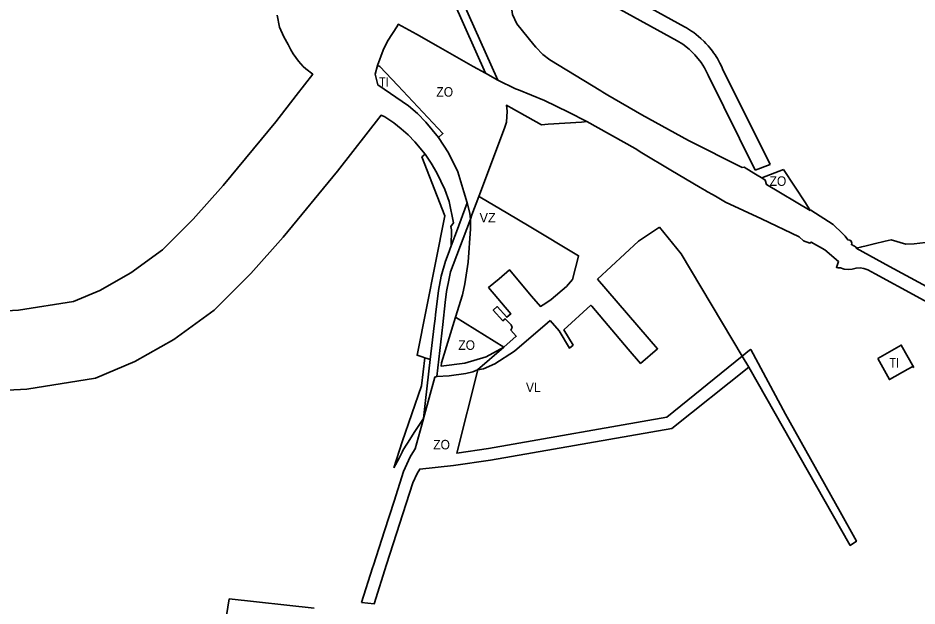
# Model space of a CAD drawing. Extents: x -650971 to -642489, y -1074311 to -1062745.
# Drawn here: x -647077 to -645941, y -1069362 to -1068619 of the extents above; entities that cross this region are included whole.
import ezdxf

# ---------------------------------------------------------------- set-up
doc = ezdxf.new("R2010")
doc.units = 0
doc.header["$LTSCALE"] = 4.8
for name, color, linetype, lineweight in [('13', 7, 'Continuous', 35), ('15', 7, 'Continuous', 35), ('24', 7, 'Continuous', 35), ('30', 7, 'Continuous', 35), ('34', 7, 'Continuous', 35), ('36', 7, 'Continuous', 35), ('42', 7, 'Continuous', 35), ('62', 7, 'Continuous', 35)]:
    doc.layers.add(name, color=color, linetype=linetype, lineweight=lineweight)

msp = doc.modelspace()

# ---------------------------------------------------------------- linework, layer by layer
at = {"layer": '13'}
msp.add_lwpolyline([(-646842.441, -1069555.283), (-646809.879, -1069353.002), (-646702.425, -1069364.771)], dxfattribs=at)
at = {"layer": '15'}
msp.add_lwpolyline([(-646161.484, -1069046.228), (-646152.26, -1069038.76), (-646150.87, -1069037.64), (-646107, -1069119.41), (-646037.99, -1069242.88), (-646017.15, -1069280.19), (-646025.14, -1069285.394), (-646153.307, -1069059.947)], close=True, dxfattribs=at)
at = {"layer": '24'}
msp.add_line((-646126.317, -1068803.654), (-646145.083, -1068810.83), dxfattribs=at)
for points in [[(-646513.45, -1068476.025), (-646234.342, -1068629.892), (-646232.141, -1068631.139), (-646229.573, -1068632.68), (-646225.838, -1068635.097), (-646222.933, -1068637.129), (-646219.751, -1068639.522), (-646216.809, -1068641.902), (-646213.784, -1068644.532), (-646209.607, -1068648.501), (-646207.455, -1068650.718), (-646204.769, -1068653.669), (-646202.389, -1068656.475), (-646200.727, -1068658.552), (-646199.218, -1068660.531), (-646197.683, -1068662.645), (-646195.834, -1068665.339), (-646194.492, -1068667.409), (-646192.895, -1068670.012), (-646191.425, -1068672.562), (-646189.676, -1068675.819), (-646187.091, -1068681.19), (-646186.901, -1068681.614), (-646186.371, -1068682.825), (-646126.317, -1068803.654)], [(-646556.22, -1068515.84), (-646555, -1068519.38), (-646526.1, -1068598.55), (-646486.23, -1068688.54)], [(-646470.65, -1068697.38), (-646515.09, -1068597.29), (-646516.07, -1068595.08), (-646519.14, -1068587.06), (-646521.81, -1068580.69), (-646535.84, -1068539.8), (-646541.06, -1068524.58), (-646545.57, -1068511.42)], [(-646495.416, -1068512.888), (-646487.92, -1068516.87), (-646477.41, -1068526.45), (-646469.51, -1068538.15), (-646461.14, -1068556.34), (-646458.03, -1068569.26), (-646451.82, -1068614.31), (-646446.54, -1068626.14), (-646425.11, -1068652.37), (-646422.32, -1068655.58), (-646413.45, -1068664.71), (-646404.83, -1068671.52), (-646340.36, -1068710.915), (-646337.93, -1068712.4), (-646331.26, -1068716.25), (-646288.59, -1068740.88), (-646229.44, -1068773.53), (-646161.45, -1068807.54), (-646159.1, -1068807.43), (-646150.26, -1068812.81)], [(-646145.083, -1068810.83), (-646204.654, -1068690.937), (-646209.179, -1068681.795), (-646213.659, -1068674.696), (-646221.348, -1068665.144), (-646228.691, -1068658.051), (-646236.707, -1068651.891), (-646243.997, -1068647.407), (-646493.511, -1068509.855)], [(-647128.674, -1068991.167), (-647076.422, -1068988.18), (-647006.63, -1068977.08), (-646973.61, -1068963.135), (-646934.465, -1068940.759), (-646894.206, -1068911.595), (-646855.506, -1068872.883), (-646817.718, -1068830.545), (-646751.116, -1068749.975), (-646725.374, -1068716.786), (-646704.316, -1068689.698), (-646712.93, -1068683), (-646716.39, -1068679.8), (-646722.6, -1068673.11), (-646729.34, -1068663.94), (-646732.25, -1068659.06), (-646735.62, -1068652.21), (-646740.91, -1068642.34), (-646746.32, -1068630.23), (-646749.35, -1068615.18)], [(-646486.23, -1068688.54), (-646501.64, -1068679.81), (-646545.73, -1068654.81), (-646573.14, -1068638.98), (-646596.28, -1068626.52), (-646597.4, -1068628.74), (-646609.7, -1068647.84), (-646615.19, -1068659.11), (-646622.68, -1068678.75)], [(-646622.68, -1068678.75), (-646625.35, -1068689.7), (-646622.01, -1068703.3), (-646583.49, -1068729.76), (-646571.91, -1068739.54), (-646561.5, -1068750.22), (-646545.32, -1068769.89)], [(-646357.87, -1068749.64), (-646380.94, -1068737.81), (-646411.3, -1068723.11), (-646444.51, -1068709.64), (-646448.02, -1068707.99), (-646470.65, -1068697.38)], [(-646562.49, -1068790.69), (-646575.28, -1068775.04), (-646583.98, -1068766.42), (-646592.53, -1068758.66), (-646601.86, -1068751.01), (-646613.44, -1068743.65), (-646617.991, -1068741.503), (-646673.05, -1068812.491), (-646741.85, -1068895.719), (-646782.784, -1068941.581), (-646829.104, -1068987.917), (-646880.163, -1069024.903), (-646929.186, -1069052.925), (-646978.92, -1069073.93), (-647065.688, -1069087.73), (-647123.648, -1069091.043), (-647197.498, -1069094.255), (-647270.522, -1069094.255), (-647344.902, -1069091.02), (-647426.417, -1069084.624), (-647511.94, -1069076.703), (-647708.401, -1069056.275), (-647756.441, -1069053.207), (-647798.631, -1069052.508)], [(-646208.7, -1068836.39), (-646214.92, -1068832.85), (-646251.73, -1068811.04), (-646288.37, -1068789.04), (-646297.08, -1068783.8), (-646357.87, -1068749.64)], [(-646545.32, -1068769.89), (-646532.92, -1068788.95), (-646521.18, -1068812.95), (-646513.27, -1068838.37), (-646509.323, -1068852.529)], [(-646529.44, -1068906.81), (-646528.92, -1068886.55), (-646530.06, -1068882.16), (-646526.64, -1068877.47), (-646532.16, -1068850.47), (-646537.35, -1068835.56), (-646547.68, -1068814.22), (-646554.8, -1068801.98), (-646562.49, -1068790.69)], [(-646150.26, -1068812.81), (-646146.85, -1068814.88), (-646140.73, -1068818.61), (-646136.99, -1068820.88)], [(-646136.99, -1068820.88), (-646132.62, -1068823.54), (-646130.68, -1068829.21), (-646075.56, -1068861.95)], [(-646195.52, -1068843.92), (-646199.24, -1068841.79), (-646205.48, -1068838.23), (-646208.7, -1068836.39)], [(-645896.91, -1068994.75), (-645940.77, -1068970.74), (-645993.5, -1068942.1), (-646002.95, -1068936.95), (-646007.7, -1068935.18), (-646012.64, -1068934.34), (-646017.6, -1068934.89), (-646022.77, -1068936.12), (-646027.69, -1068936.6), (-646032.61, -1068936.1), (-646037.5, -1068934.7), (-646040.65, -1068934.59), (-646042.5, -1068933.91), (-646039.84, -1068926.67), (-646057.13, -1068911.62), (-646074.51, -1068901.9), (-646076.09, -1068903.48), (-646084.1, -1068900.51), (-646089.63, -1068895.5), (-646137.23, -1068872.6), (-646182.57, -1068851.3), (-646195.52, -1068843.92)], [(-646509.323, -1068852.529), (-646510.56, -1068855.86), (-646521.63, -1068885.74), (-646529.44, -1068906.81)], [(-646075.56, -1068861.95), (-646074.78, -1068861.51), (-646046.48, -1068879.92), (-646034.65, -1068891.12), (-646031.31, -1068894.32), (-646028.18, -1068898.89), (-646025.57, -1068899.39), (-646023.92, -1068900.73), (-646023.13, -1068903.12), (-646023.56, -1068905.05), (-646017.39, -1068908.42), (-646017.55, -1068909.75)], [(-646547.413, -1069071.71), (-646539.77, -1069006.25), (-646537.02, -1068978.44), (-646535.13, -1068964.38), (-646532.13, -1068948), (-646530.08, -1068939.43), (-646526.81, -1068930.69), (-646505.17, -1068872.78)], [(-646505.17, -1068872.78), (-646505.12, -1068885.31), (-646507.91, -1068927.47), (-646512.07, -1068954.68), (-646514.91, -1068968.48), (-646524, -1068997)], [(-646017.55, -1068909.75), (-645975.31, -1068932.8), (-645933.28, -1068955.74), (-645892.77, -1068977.86), (-645856.26, -1068997.79)], [(-646524, -1068997), (-646541.71, -1069054.76), (-646542, -1069059), (-646512, -1069055), (-646485, -1069047), (-646462.98, -1069034.61), (-646496.317, -1069063.61)], [(-646601.82, -1069187.25), (-646591.26, -1069154.54), (-646566.82, -1069083.62), (-646562.61, -1069048.08)], [(-646555.84, -1069050.22), (-646561.88, -1069102.18), (-646562.35, -1069106.21), (-646564.54, -1069125.08)], [(-646562.61, -1069048.08), (-646559.8, -1069048.98), (-646555.84, -1069050.22)], [(-646496.317, -1069063.61), (-646502, -1069066), (-646511, -1069068), (-646532, -1069071), (-646547.413, -1069071.71)], [(-646564.54, -1069125.08), (-646575.4, -1069141.46), (-646582.46, -1069152.81), (-646583.89, -1069155.1), (-646585.42, -1069157.56), (-646586.97, -1069160.06), (-646590.38, -1069165.55), (-646591.4, -1069167.48), (-646595.32, -1069174.92), (-646601.82, -1069187.25)]]:
    msp.add_lwpolyline(points, dxfattribs=at)
at = {"layer": '30'}
for points in [[(-646545.32, -1068769.89), (-646561.5, -1068750.22), (-646571.91, -1068739.54), (-646583.49, -1068729.76), (-646622.01, -1068703.3), (-646625.35, -1068689.7), (-646622.68, -1068678.75)], [(-646622.68, -1068678.75), (-646619.74, -1068680.15), (-646596.93, -1068704.15), (-646539.78, -1068764.65), (-646545.32, -1068769.89)], [(-646562.61, -1069048.08), (-646566.25, -1069046.92), (-646572.42, -1069044.94), (-646537.3, -1068868.95), (-646566.34, -1068794.32), (-646562.49, -1068790.69)], [(-646562.49, -1068790.69), (-646554.8, -1068801.98), (-646547.68, -1068814.22), (-646537.35, -1068835.56), (-646532.16, -1068850.47), (-646526.64, -1068877.47), (-646530.06, -1068882.16), (-646528.92, -1068886.55), (-646529.44, -1068906.81)], [(-646529.44, -1068906.81), (-646533.28, -1068917.17), (-646536.54, -1068925.95), (-646542.16, -1068945.12), (-646545.42, -1068963.3), (-646549.17, -1068993.71), (-646549.81, -1068998.88), (-646550.89, -1069007.7), (-646555.84, -1069050.22)], [(-645990.13, -1069049.3), (-645960.67, -1069032.26), (-645944.69, -1069060.7)], [(-646555.84, -1069050.22), (-646559.8, -1069048.98), (-646562.61, -1069048.08)], [(-645944.69, -1069060.7), (-645946.84, -1069059.58), (-645952.21, -1069062.4), (-645975.48, -1069075.71), (-645990.13, -1069049.3)]]:
    msp.add_lwpolyline(points, dxfattribs=at)
at = {"layer": '34'}
for points in [[(-646344.49, -1068948.736), (-646292.75, -1068900.72), (-646266.118, -1068883.048)], [(-646266.118, -1068883.048), (-646238.632, -1068916.799), (-646161.484, -1069046.228)], [(-646404.269, -1069001.033), (-646393.09, -1069014.234), (-646379.973, -1069035.889), (-646375.346, -1069032.07), (-646386.936, -1069012.936), (-646352.71, -1068981.82), (-646351.638, -1068983.08), (-646351.641, -1068983.083), (-646305.65, -1069037.39), (-646290.099, -1069055.423), (-646268.528, -1069036.82), (-646344.49, -1068948.736)], [(-646495.89, -1069063.531), (-646488.537, -1069062.169), (-646474.13, -1069055.83), (-646449.419, -1069039.805), (-646425.52, -1069019.41), (-646410.96, -1069006.99), (-646404.269, -1069001.033)], [(-646161.484, -1069046.228), (-646256.824, -1069123.414), (-646482.211, -1069162.813), (-646522.35, -1069168.648), (-646495.89, -1069063.531)]]:
    msp.add_lwpolyline(points, dxfattribs=at)
at = {"layer": '36'}
for points in [[(-646494.52, -1068844.29), (-646492.73, -1068845.01), (-646457.86, -1068865.8), (-646430.86, -1068881.89), (-646368.3, -1068919.19), (-646368.42, -1068919.59), (-646376.02, -1068949.34), (-646383.86, -1068958.24), (-646403.13, -1068974.41), (-646409.67, -1068979.3), (-646416.71, -1068983.21), (-646427.77, -1068970.39), (-646455.78, -1068936.87), (-646468.83, -1068948.26), (-646482.2, -1068959.52), (-646454.21, -1068992.73), (-646459.25, -1068996.98), (-646471.24, -1068983.41), (-646476.35, -1068987.98), (-646464.24, -1069001.49), (-646461.29, -1068998.81), (-646453.48, -1069006.75), (-646452.37, -1069010.01), (-646453.88, -1069013.1), (-646447.2, -1069020.9), (-646462.98, -1069034.61), (-646524, -1068997)], [(-646505.17, -1068872.78), (-646503.24, -1068867.61), (-646494.52, -1068844.29)], [(-646524, -1068997), (-646514.91, -1068968.48), (-646512.07, -1068954.68), (-646507.91, -1068927.47), (-646505.12, -1068885.31), (-646505.17, -1068872.78)]]:
    msp.add_lwpolyline(points, dxfattribs=at)
at = {"layer": '42'}
for p, q in [((-646136.99, -1068820.88), (-646109.35, -1068810.23)), ((-646524, -1068997), (-646462.98, -1069034.61))]:
    msp.add_line(p, q, dxfattribs=at)
for points in [[(-646622.68, -1068678.75), (-646615.19, -1068659.11), (-646609.7, -1068647.84), (-646597.4, -1068628.74), (-646596.28, -1068626.52), (-646573.14, -1068638.98), (-646545.73, -1068654.81), (-646501.64, -1068679.81), (-646486.23, -1068688.54), (-646470.65, -1068697.38)], [(-646545.32, -1068769.89), (-646539.78, -1068764.65), (-646596.93, -1068704.15), (-646619.74, -1068680.15), (-646622.68, -1068678.75)], [(-646470.65, -1068697.38), (-646448.02, -1068707.99), (-646444.51, -1068709.64), (-646411.3, -1068723.11), (-646380.94, -1068737.81), (-646357.87, -1068749.64)], [(-646357.87, -1068749.64), (-646364.77, -1068750.16), (-646406.7, -1068753.03), (-646415.3, -1068753.62), (-646453.51, -1068732.3), (-646459.54, -1068728.94), (-646458.57, -1068736.31), (-646459.59, -1068750.19), (-646461.92, -1068757.93), (-646494.52, -1068844.29)], [(-646509.323, -1068852.529), (-646513.27, -1068838.37), (-646521.18, -1068812.95), (-646532.92, -1068788.95), (-646545.32, -1068769.89)], [(-646109.35, -1068810.23), (-646081.72, -1068852.51), (-646075.56, -1068861.95)], [(-646075.56, -1068861.95), (-646130.68, -1068829.21), (-646132.62, -1068823.54), (-646136.99, -1068820.88)], [(-646494.52, -1068844.29), (-646503.24, -1068867.61), (-646505.17, -1068872.78)], [(-646505.17, -1068872.78), (-646505.69, -1068865.56), (-646509.323, -1068852.529)], [(-646017.55, -1068909.75), (-646010.48, -1068907.86), (-646004.88, -1068906.5), (-645994.9, -1068904.1), (-645980.93, -1068900.85), (-645973.36, -1068898.93)], [(-645973.36, -1068898.93), (-645954.59, -1068904.41), (-645944.23, -1068904.13), (-645930.1, -1068902.47), (-645915.61, -1068901.02), (-645902.91, -1068901.43), (-645882.63, -1068905.88), (-645856.26, -1068997.79)], [(-645856.26, -1068997.79), (-645892.77, -1068977.86), (-645933.28, -1068955.74), (-645975.31, -1068932.8), (-646017.55, -1068909.75)], [(-646462.98, -1069034.61), (-646485, -1069047), (-646512, -1069055), (-646542, -1069059), (-646541.71, -1069054.76), (-646524, -1068997)], [(-646495.89, -1069063.531), (-646522.35, -1069168.648), (-646482.211, -1069162.813), (-646256.824, -1069123.414), (-646161.484, -1069046.228), (-646153.307, -1069059.947)], [(-646153.307, -1069059.947), (-646250.409, -1069137.52), (-646479.84, -1069177.626), (-646526.31, -1069184.381), (-646569.114, -1069188.86), (-646572.586, -1069194.485), (-646577.878, -1069206.485), (-646611.107, -1069309.68), (-646626.774, -1069359.349), (-646642.89, -1069357.68)], [(-646547.413, -1069071.71), (-646532, -1069071), (-646511, -1069068), (-646502, -1069066), (-646496.317, -1069063.61), (-646495.89, -1069063.531)], [(-646564.54, -1069125.08), (-646549.91, -1069072.542), (-646547.413, -1069071.71)], [(-646642.89, -1069357.68), (-646628.66, -1069313.66), (-646627.59, -1069310.34), (-646613.6, -1069267.04), (-646601.41, -1069229.34), (-646589.56, -1069192.07), (-646581.29, -1069173.32), (-646575.87, -1069164.54), (-646575.015, -1069163.152), (-646564.605, -1069125.271), (-646564.54, -1069125.08)]]:
    msp.add_lwpolyline(points, dxfattribs=at)

# ---------------------------------------------------------------- texts
at = {"layer": '62'}
for s, width, p in [('TI', 0.85, (-646620.476, -1068705.535)), ('ZO', 0.95, (-646548.118, -1068718.035)), ('ZO', 0.95, (-646127.027, -1068830.859)), ('ZO', 0.95, (-646520.423, -1069038.188)), ('TI', 0.85, (-645975.476, -1069060.535)), ('VL', 0.95, (-646434.928, -1069091.6)), ('ZO', 0.95, (-646552.118, -1069164.035))]:
    msp.add_text(s, height=12, dxfattribs=dict(at, width=width)).set_placement(p)
msp.add_text('VZ', height=12, dxfattribs=at).set_placement((-646493.598, -1068877.069))

doc.saveas('drawing.dxf')
